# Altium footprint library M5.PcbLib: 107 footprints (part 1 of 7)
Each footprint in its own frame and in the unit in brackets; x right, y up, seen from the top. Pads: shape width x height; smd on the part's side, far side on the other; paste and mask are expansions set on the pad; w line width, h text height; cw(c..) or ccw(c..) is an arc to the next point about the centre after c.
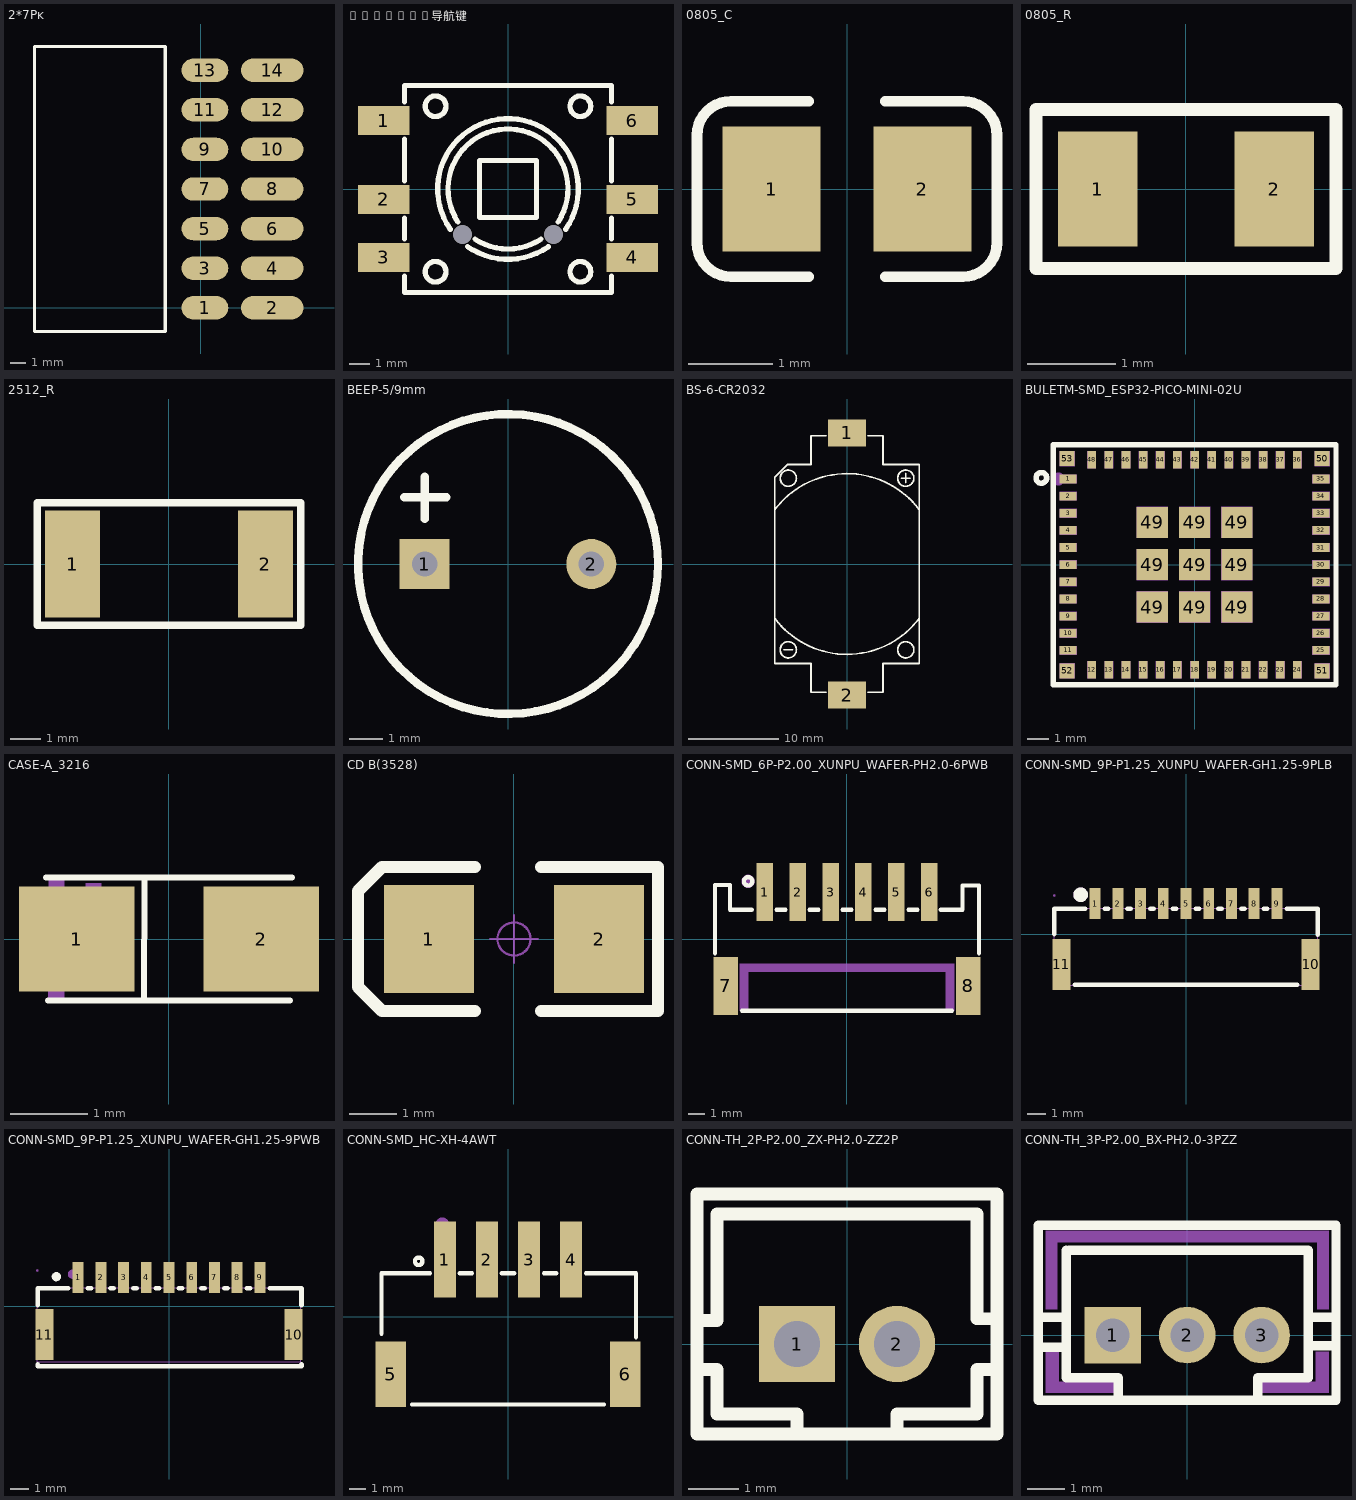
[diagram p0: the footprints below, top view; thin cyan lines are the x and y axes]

## 2*7Pĸ [mm]
pads (14):
  oval 3x1.5 smd: 1(0.254,0) 3(0.254,2.54) 5(0.254,5.08) 7(0.254,7.62) 9(0.254,10.16) 11(0.254,12.7) 13(0.254,15.24)
  oval 4x1.5 smd: 2(4.572,0) 4(4.572,2.54) 6(4.572,5.08) 8(4.572,7.62) 10(4.572,10.16) 12(4.572,12.7) 14(4.572,15.24)
Top Overlay:
  lines w0.2: -10.668,-1.524 -2.286,-1.524 -2.286,16.764 -10.668,16.764 -10.668,-1.524

## 10*10*9导航键 [mm]
pads (8):
  rect 2.5x1.4 smd: 1(-6,3.3) 2(-6,-0.5) 3(-6,-3.3) 4(6,-3.3) 5(6,-0.5) 6(6,3.3)
  round 0.9 hole 0.9: ""(-2.2,-2.2) ""(2.2,-2.2)
Top Overlay:
  circle w0.254: c-3.5,-4 r0.5
  circle w0.254: c3.5,-4 r0.5
  circle w0.254: c3.5,4 r0.5
  circle w0.254: c-3.5,4 r0.5
  lines w0.254: -5,-4.2 -5,-5 5,-5 5,-4.2 ; -5,-2.4 -5,-1.4 ; -5,0.4 -5,2.4 ; -5,4.2 -5,5 5,5 5,4.2 ; -2.789,-1.945 cw(c0,0) 2.79,-1.943 ; -2.421,-1.597 cw(c0,0) 2.421,-1.597 ; -1.955,-2.782 ccw(c0,0) 1.95,-2.785 ; -1.597,-2.421 ccw(c0,0) 1.596,-2.421 ; 5,-2.4 5,-1.4 ; 5,0.4 5,2.4 ; -1.375,-1.375 -1.375,1.375 1.375,1.375 1.375,-1.375 -1.375,-1.375

## 0805_C [mm]
pads (2):
  rect 1.16x1.47 smd: 1(-0.89,0) 2(0.89,0)
Top Overlay:
  lines w0.127: -0.45,-1.035 -1.37,-1.035 cw(c-1.37,-0.635) -1.77,-0.635 -1.77,0.635 cw(c-1.37,0.635) -1.37,1.035 -0.45,1.035 ; 0.45,-1.035 1.37,-1.035 ccw(c1.37,-0.635) 1.77,-0.635 1.77,0.635 ccw(c1.37,0.635) 1.37,1.035 0.45,1.035

## 0805_R [mm]
pads (2):
  rect 0.9x1.3 smd: 1(-1,0) 2(1,0)
Top Overlay:
  lines w0.15: -1.7,-0.9 1.7,-0.9 1.7,0.9 -1.7,0.9 -1.7,-0.9
3D body: height 0.5, standoff 0, extent -0.975,-0.625 1.025,0.625

## 2512_R [mm]
pads (2):
  rect 1.8x3.5 smd: 1(-3.15,0) 2(3.15,0)
Top Overlay:
  lines w0.25: -4.3,-2 -4.3,2 4.3,2 4.3,-2 -4.3,-2

## BEEP-5/9mm [mm]
height 2.65
pads (2):
  rect 1.5x1.5 hole 0.762: 1(-2.5,0)
  round 1.5 hole 0.762: 2(2.5,0)
Top Overlay:
  circle w0.254: c0,0 r4.5
  lines w0.254: -3.115,2 -1.845,2 ; -2.5,1.35 -2.5,2.62
3D body: height 5.5, standoff -5.5, extent -4.555,-4.5 4.445,4.5

## BS-6-CR2032 [mm]
pads (2):
  rect 4.2x3 smd: 1(0,14.5) 2(0,-14.5)
Top Overlay:
  circle w0.2: c6.5,9.5 r0.894
  circle w0.2: c-6.5,9.5 r0.894
  circle w0.2: c-6.5,-9.5 r0.894
  circle w0.2: c6.5,-9.5 r0.894
  lines w0.2: -8,6 cw(c0,0) 7.964,6.048 ; -7.964,-6.048 ccw(c0,0) 8,-6 ; -7,-9.5 -6,-9.5 ; -2.3,-14.2 -4,-14.2 -4,-11 -8,-11 -8,0 -8,9.6 -6.6,11 -4,11 -4,14.2 -2.3,14.2 ; 2.3,-14.2 4,-14.2 4,-11 8,-11 8,0 8,11 4,11 4,14.2 2.3,14.2 ; 6,9.5 7,9.5 ; 6.5,9 6.5,10

## BULETM-SMD_ESP32-PICO-MINI-02U [mm]
pads (61):
  rect 0.8x0.4 smd paste+0 mask+0.05: 1(-5.9,4) 2(-5.9,3.2) 3(-5.9,2.4) 4(-5.9,1.6) 5(-5.9,0.8) 6(-5.9,0) 7(-5.9,-0.8) 8(-5.9,-1.6) 9(-5.9,-2.4) 10(-5.9,-3.2) 11(-5.9,-4) 25(5.9,-4) 26(5.9,-3.2) 27(5.9,-2.4) 28(5.9,-1.6) 29(5.9,-0.8) 30(5.9,0) 31(5.9,0.8) 32(5.9,1.6) 33(5.9,2.4) 34(5.9,3.2) 35(5.9,4)
  rect 0.4x0.8 smd paste+0 mask+0.05: 12(-4.8,-4.9) 13(-4,-4.9) 14(-3.2,-4.9) 15(-2.4,-4.9) 16(-1.6,-4.9) 17(-0.8,-4.9) 18(0,-4.9) 19(0.8,-4.9) 20(1.6,-4.9) 21(2.4,-4.9) 22(3.2,-4.9) 23(4,-4.9) 24(4.8,-4.9) 36(4.8,4.9) 37(4,4.9) 38(3.2,4.9) 39(2.4,4.9) 40(1.6,4.9) 41(0.8,4.9) 42(0,4.9) 43(-0.8,4.9) 44(-1.6,4.9) 45(-2.4,4.9) 46(-3.2,4.9) 47(-4,4.9) 48(-4.8,4.9)
  rect 1.45x1.45 smd paste+0 mask+0.05: 49(-1.975,-1.975) 49(-1.975,0) 49(-1.975,1.975) 49(0,-1.975) 49(0,0) 49(0,1.975) 49(1.975,-1.975) 49(1.975,0) 49(1.975,1.975)
  rect 0.7x0.7 smd paste+0 mask+0.05: 50(5.95,4.95) 51(5.95,-4.95) 52(-5.95,-4.95) 53(-5.95,4.95)
Top Overlay:
  circle w0.254: c-7.15,4.05 r0.25
  lines w0.254: -6.6,4.85 -6.6,5.6 6.6,5.6 6.6,-5.6 -6.6,-5.6 -6.6,4.95
Mechanical 6:
  circle w0.3: c-6.35,4 r0.15
Mechanical 15:
  drawing of 66 lines, arcs and shapes, not listed
3D body: height 2.75, standoff -0.1, extent -6.6,-5.6 6.6,5.6

## CASE-A_3216 [mm]
pads (2):
  rect 1.5x1.359 smd: 1(-1.2,0) 2(1.2,0)
Top Overlay:
  lines w0.08: -1.6,0.8 1.6,0.8 ; -1.575,-0.8 1.575,-0.8 ; -0.323,-0.8 -0.32,0.8
Mechanical 6:
  region: 1.501,0.13 1.501,-0.08 0.661,-0.08 0.661,0.13
  region: -1.563,0.813 -1.36,0.813 -1.36,0.483 -1.563,0.483
  region: -1.363,-0.813 -1.567,-0.813 -1.567,-0.483 -1.363,-0.483
  region: -0.61,0.13 -0.61,-0.08 -1.45,-0.08 -1.45,0.13
  region: -1.081,0.724 -0.878,0.724 -0.878,-0.673 -1.081,-0.673
3D body: height 1.8, standoff 0, extent -1.6,-0.775 1.6,0.775

## CD B(3528) [mm]
pads (2):
  rect 1.905x2.286 smd: 1(-1.8,0) 2(1.8,0)
Top Overlay:
  lines w0.254: -0.825,-1.524 -2.794,-1.524 -3.302,-1.016 -3.302,1.016 -2.794,1.524 -0.825,1.524 ; 0.572,-1.524 3.048,-1.524 3.048,1.524 0.572,1.524
Mechanical 15:
  circle w0.05: c0,0 r0.35
  lines w0.05: -0.5,0 0.5,0 ; 0,-0.5 0,0.5
3D body: height 1.9, standoff -0.01, extent -1.75,-1.4 1.75,1.4

## CONN-SMD_6P-P2.00_XUNPU_WAFER-PH2.0-6PWB [mm]
pads (8):
  rect 1x3.5 smd paste+0 mask+0.05: 1(-5,2.85) 2(-3,2.85) 3(-1,2.85) 4(1,2.85) 5(3,2.85) 6(5,2.85)
  rect 1.5x3.5 smd paste+0 mask+0.05: 7(-7.35,-2.85) 8(7.35,-2.85)
Top Overlay:
  circle w0.254: c-6,3.5 r0.254
  lines w0.254: -8,-0.869 -8,3.24 ; -8,3.279 -7.097,3.279 -7.097,1.78 -5.779,1.78 ; -6.369,-4.35 6.369,-4.35 ; -4.269,1.78 -3.731,1.78 ; -2.269,1.78 -1.731,1.78 ; -0.269,1.78 0.269,1.78 ; 1.731,1.78 2.269,1.78 ; 3.731,1.78 4.269,1.78 ; 5.683,1.78 7.001,1.78 7.001,3.24 ; 7,3.24 8,3.24 8,-0.869
Mechanical 6:
  circle w0.4: c-6,3.5 r0.2
  region: -6.5,-4.35 -6.5,-1.5 6.5,-1.5 6.5,-4.35 6,-4.35 6,-2 -6,-2 -6,-4.35
3D body: height 5.59, standoff -0.01, extent -8.001,-4.377 7.999,4.123

## CONN-SMD_9P-P1.25_XUNPU_WAFER-GH1.25-9PLB [mm]
pads (11):
  rect 0.6x1.7 smd: 1(-5,1.675) 2(-3.75,1.675) 3(-2.5,1.675) 4(-1.25,1.675) 5(0,1.675) 6(1.25,1.675) 7(2.5,1.675) 8(3.75,1.675) 9(5,1.675)
  rect 1x2.8 smd: 10(6.85,-1.675) 11(-6.85,-1.675)
Top Overlay:
  circle w0.4: c-5.792,2.159 r0.2
  lines w0.254: -7.25,0 -7.25,1.397 -5.531,1.397 ; -6.119,-2.794 3.619,-2.794 6.119,-2.794 ; -4.469,1.397 -4.281,1.397 ; -3.219,1.397 -3.031,1.397 ; -1.969,1.397 -1.781,1.397 ; -0.719,1.397 -0.531,1.397 ; 0.531,1.397 0.719,1.397 ; 1.781,1.397 1.969,1.397 ; 3.031,1.397 3.219,1.397 ; 4.281,1.397 4.469,1.397 ; 5.531,1.397 7.239,1.397 7.239,-0.044
Mechanical 6:
  circle w0.4: c-5.792,2.159 r0.2
Mechanical 15:
  region: -7.185,2.122 -7.204,2.076 -7.25,2.057 -7.296,2.076 -7.315,2.122 -7.296,2.168 -7.25,2.187 -7.204,2.168
  region: 5.1,1.322 4.9,1.322 4.9,2.122 5.1,2.122
  region: 3.85,1.322 3.65,1.322 3.65,2.122 3.85,2.122
  region: -1.15,1.322 -1.35,1.322 -1.35,2.122 -1.15,2.122
  region: -2.4,1.322 -2.6,1.322 -2.6,2.122 -2.4,2.122
  region: -3.65,1.322 -3.85,1.322 -3.85,2.122 -3.65,2.122
  region: -4.9,1.322 -5.1,1.322 -5.1,2.122 -4.9,2.122
  region: 0.1,1.322 -0.1,1.322 -0.1,2.122 0.1,2.122
  region: 1.35,1.322 1.15,1.322 1.15,2.122 1.35,2.122
  region: 2.6,1.322 2.4,1.322 2.4,2.122 2.6,2.122
  region: -6.75,-2.425 -6.95,-2.425 -6.95,-0.925 -6.75,-0.925
  region: 6.95,-2.425 6.75,-2.425 6.75,-0.925 6.95,-0.925
  lines w0.051: -7.25,-2.828 -7.25,1.422 7.25,1.422 7.25,-2.828 -7.25,-2.828
3D body: height 4.05, standoff -0.1, extent -7.261,-2.921 7.239,2.029

## CONN-SMD_9P-P1.25_XUNPU_WAFER-GH1.25-9PWB [mm]
pads (11):
  rect 0.6x1.7 smd paste+0 mask+0.05: 1(-5,1.575) 2(-3.75,1.575) 3(-2.5,1.575) 4(-1.25,1.575) 5(0,1.575) 6(1.25,1.575) 7(2.5,1.575) 8(3.75,1.575) 9(5,1.575)
  rect 1x2.8 smd paste+0 mask+0.05: 10(6.85,-1.575) 11(-6.85,-1.575)
Top Overlay:
  circle w0.254: c-6.197,1.613 r0.127
  lines w0.254: -7.213,-3.206 -7.213,-3.304 7.239,-3.304 ; -7.213,0.056 -7.213,0.978 -5.531,0.978 ; -4.469,0.978 -4.281,0.978 ; -3.219,0.978 -3.031,0.978 ; -1.969,0.978 -1.781,0.978 ; -0.719,0.978 -0.531,0.978 ; 0.531,0.978 0.719,0.978 ; 1.781,0.978 1.969,0.978 ; 3.031,0.978 3.219,0.978 ; 4.281,0.978 4.469,0.978 ; 5.531,0.978 7.287,0.978 7.287,0.056 ; 7.287,-3.304 7.287,-3.206
Mechanical 6:
  circle w0.254: c-5.311,1.75 r0.127
Mechanical 15:
  region: -7.185,1.945 -7.204,1.899 -7.25,1.88 -7.296,1.899 -7.315,1.945 -7.296,1.991 -7.25,2.01 -7.204,1.991
  region: 4.9,1.945 5.1,1.945 5.1,0.845 4.9,0.845
  region: 3.65,1.945 3.85,1.945 3.85,0.845 3.65,0.845
  region: -0.1,1.945 0.1,1.945 0.1,0.845 -0.1,0.845
  region: 1.15,1.945 1.35,1.945 1.35,0.845 1.15,0.845
  region: 2.4,1.945 2.6,1.945 2.6,0.845 2.4,0.845
  region: -1.35,1.945 -1.15,1.945 -1.15,0.845 -1.35,0.845
  region: -2.6,1.945 -2.4,1.945 -2.4,0.845 -2.6,0.845
  region: -3.85,1.945 -3.65,1.945 -3.65,0.845 -3.85,0.845
  region: -5.1,1.945 -4.9,1.945 -4.9,0.845 -5.1,0.845
  region: -6.95,-0.575 -6.75,-0.575 -6.75,-2.575 -6.95,-2.575
  region: 6.75,-0.575 6.95,-0.575 6.95,-2.575 6.75,-2.575
  lines w0.051: -7.25,-3.055 -7.25,0.995 7.25,0.995 7.25,-3.055 -7.25,-3.055
3D body: height 4.25, standoff -0.1, extent -7.25,-3.175 7.25,1.825

## CONN-SMD_HC-XH-4AWT [mm]
pads (6):
  rect 1.3x4.5 smd paste+0 mask+0.05: 1(-3.75,3.4) 2(-1.25,3.4) 3(1.25,3.4) 4(3.75,3.4)
  rect 1.8x3.9 smd paste+0 mask+0.05: 5(-6.95,-3.4) 6(6.95,-3.4)
Top Overlay:
  circle w0.254: c-5.3,3.302 r0.224
  lines w0.254: -7.5,-0.998 -7.5,2.602 -4.7,2.602 -4.631,2.602 ; -5.7,-5.198 5.7,-5.198 ; -2.869,2.602 -2.131,2.602 ; -0.369,2.602 0.369,2.602 ; 2.131,2.602 2.869,2.602 ; 4.631,2.602 7.6,2.602 7.6,-1.198
Mechanical 6:
  circle w0.4: c-3.9,5.502 r0.2
3D body: height 6.02, standoff -0.03, extent -7.5,-5.423 7.5,4.977

## CONN-TH_2P-P2.00_ZX-PH2.0-ZZ2P [mil]
pads (2):
  rect 60x60 hole 35.98: 1(-39.37,0)
  round 60 hole 35.98: 2(39.37,0)
Top Overlay:
  lines w10: -118.11,-20 -102.36,-20 -102.36,-55.12 -39.41,-55.12 -39.41,-68.9 ; -118.11,18.5 -102.36,18.5 -102.36,102.36 102.36,102.36 102.36,20 118.09,20 ; 39.41,-68.9 39.41,-55.12 102.36,-55.12 102.36,-20 118.11,-20 ; -118.11,-70.87 118.11,-70.87 118.11,118.11 -118.11,118.11 -118.11,-70.87
3D body: height 243.31, standoff -128.74, extent -118.7,-68.98 118.7,120

## CONN-TH_3P-P2.00_BX-PH2.0-3PZZ [mil]
pads (3):
  rect 60x60 hole 35.43: 1(-78.74,0)
  round 60 hole 35.43: 2(0,0) 3(78.74,0)
Top Overlay:
  lines w10: -157.48,-10.43 -157.48,-12.66 -128.15,-12.66 ; -157.48,18.83 -128.15,18.83 -128.15,18.09 ; -128.15,90 -128.15,-45 -72.85,-45 -72.85,-68.9 ; -125.05,90 123.15,90 128.15,90 128.15,-45.3 74.85,-45.3 74.85,-68.9 ; 128.14,-10.43 128.14,-11.17 157.47,-11.17 ; 128.14,18.83 157.47,18.83 157.47,16.6 ; -157.48,-68.9 157.48,-68.9 157.48,116.14 -157.48,116.14 -157.48,-68.9
Mechanical 6:
  region: -149.61,-17.72 -135.83,-17.72 -135.83,-49.21 -76.77,-49.21 -76.77,-61.02 -149.61,-61.02
  region: 149.61,-17.72 135.82,-17.72 135.82,-49.21 76.77,-49.21 76.77,-61.02 149.61,-61.02
  region: -149.61,27.56 -137.79,27.56 -137.79,98.42 137.79,98.42 137.79,27.56 149.61,27.56 149.61,110.24 -149.61,110.24
Mechanical 15:
  region: -154.92,-68.9 -155.67,-67.09 -157.48,-66.34 -159.29,-67.09 -160.04,-68.9 -159.29,-70.71 -157.48,-71.46 -155.67,-70.71 -154.92,-68.9
  region: -88.58,9.84 -68.9,9.84 -68.9,-9.84 -88.58,-9.84
  region: -9.84,9.84 9.84,9.84 9.84,-9.84 -9.84,-9.84
  region: 68.9,9.84 88.58,9.84 88.58,-9.84 68.9,-9.84
  lines w2: -157.48,-68.9 -157.48,116.14 157.48,116.14 157.48,-68.9 -157.48,-68.9
3D body: height 235.04, standoff -138.98, extent -159.06,-70 159.06,116.61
